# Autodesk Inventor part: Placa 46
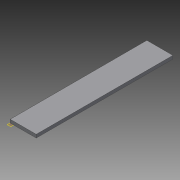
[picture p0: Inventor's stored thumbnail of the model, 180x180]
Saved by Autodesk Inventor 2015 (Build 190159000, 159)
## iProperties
Created: 2015-04
Part Number: Placa 46
Material: Generic
Document SubType Name: Modeling
Designer: suporte
Density: 1 g/cm^3
Appearance: Default
Author: suporte
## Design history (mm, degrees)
workplane "Work Plane1"
sketch "Sketch1"
  geometry: L1 (-606.25, 275)-(8.75, 275) reference; L2 (-6.25, -250)-(93.75, -250); L3 (93.75, -250)-(93.75, 275); L4 (93.75, 275)-(-6.25, 275); L5 (-6.25, 275)-(-6.25, -250); L6 (93.75, -237.5)-(93.75, 162.5) reference; 1 further point
  constraints: 8 end point, 2 parallel, 1 horizontal, 1 perpendicular, 1 point on line, 1 other
extrude "Extrusion1" new body sketch "Sketch1" distance "d0" = 12.5; taper "d1" = 0 deg
body "Solid1"
node "Reference1"
node "Reference2"
